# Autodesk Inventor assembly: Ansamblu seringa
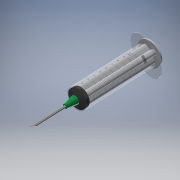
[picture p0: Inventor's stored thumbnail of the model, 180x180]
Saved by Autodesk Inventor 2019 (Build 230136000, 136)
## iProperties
Created: 2020-11
Part Number: Ansamblu seringa
Document SubType Name: Assembly
Designer: bianc
Author: bianc
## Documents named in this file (4)
- C:\Users\bianc\Documents\Ansamblu seringa.iam
- C:\Users\bianc\Desktop\DIIM\Ansamblu Seringa\ac.ipt
- C:\Users\bianc\Desktop\DIIM\Ansamblu Seringa\corp.ipt
- C:\Users\bianc\Desktop\DIIM\Ansamblu Seringa\piston.ipt
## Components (3 placed, 3 different names)
1. ac:1 — Mate:1, Mate:2, Mate:3, Rotational:1, Mate:4
2. corp:1 — Mate:1, Mate:2, Mate:3, Rotational:1, Cylindrical:1, Mate:4, Mate:5, Mate:6, Mate:7
3. piston:1 — Cylindrical:1, Mate:5, Mate:6, Mate:7
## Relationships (9: Mate 7, RevoluteJoint 1, CylindricalJoint 1)
- Mate:1: ac:1 ↔ corp:1
- Mate:2: ac:1 ↔ corp:1
- Mate:3: ac:1 ↔ corp:1
- Rotational:1 [RevoluteJoint]: ac:1 ↔ corp:1
- Cylindrical:1: corp:1 ↔ piston:1
- Mate:4: ac:1 ↔ corp:1
- Mate:5: corp:1 ↔ piston:1
- Mate:6: corp:1 ↔ piston:1
- Mate:7: corp:1 ↔ piston:1
